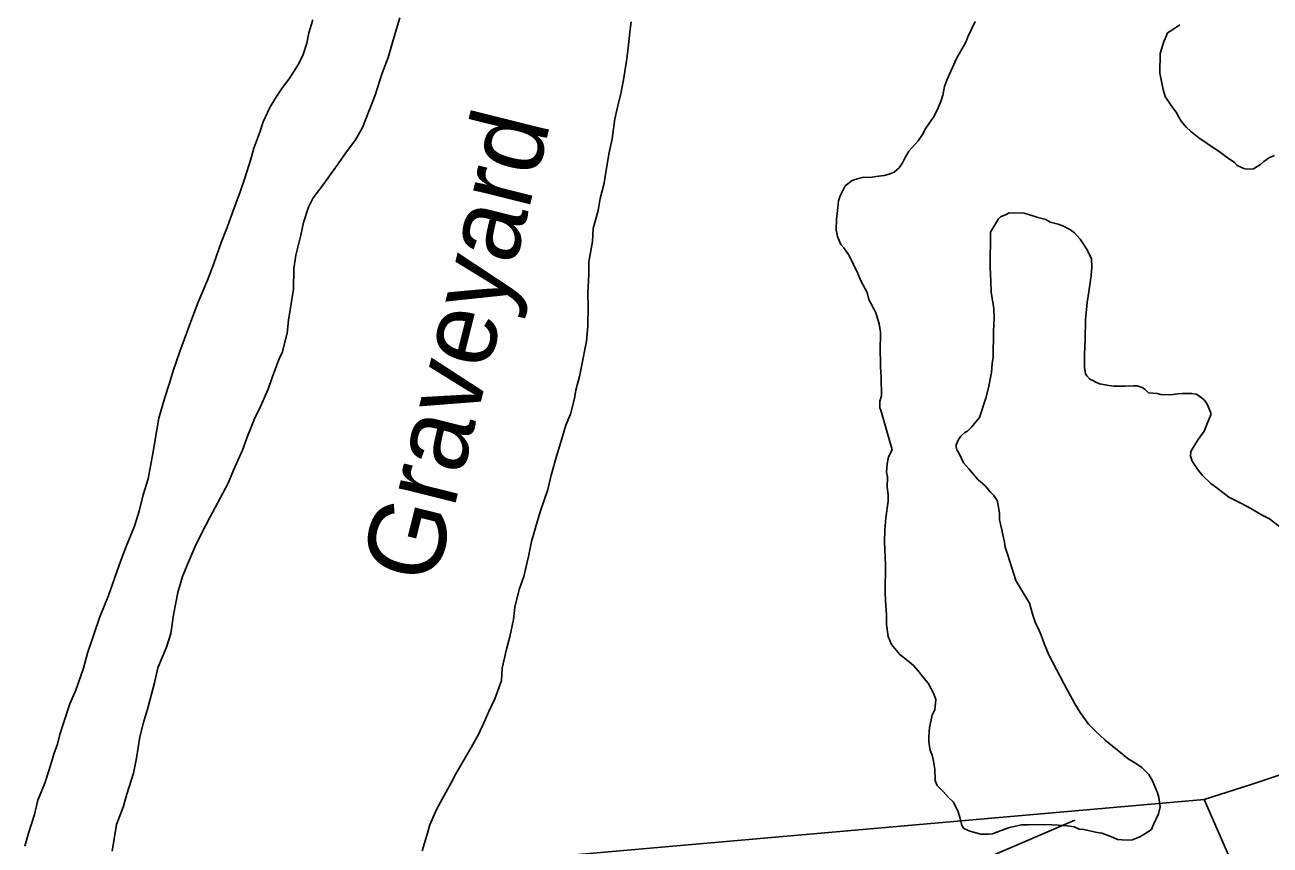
# Model space of a CAD drawing. Extents: x 3161514 to 3199414, y 831166 to 856601.
# Drawn here: x 3169027 to 3170653, y 839105 to 840176 of the extents above; entities that cross this region are included whole.
import ezdxf

# ---------------------------------------------------------------- set-up
doc = ezdxf.new("R2010")
doc.units = 0
for name, color, linetype in [('V-RIVR-IDEN', 7, 'Continuous'), ('V-SITE-VEGE', 7, 'Continuous'), ('V-TOPO-SHOR', 7, 'Continuous')]:
    doc.layers.add(name, color=color, linetype=linetype)

msp = doc.modelspace()

# ---------------------------------------------------------------- linework, layer by layer
at = {"layer": 'V-SITE-VEGE'}
for p, q in [((3169516.6, 840185.6), (3169511.2, 840166.9)), ((3169397.9, 840165.9), (3169403.2, 840182.9)), ((3169817.2, 840167), (3169819, 840180.6)), ((3170268, 840180.8), (3170258.7, 840160.8)), ((3170519.3, 840166.3), (3170523.9, 840168.9)), ((3170523.9, 840168.9), (3170535.7, 840176.5)), ((3169390.7, 840137.9), (3169395.2, 840152.4)), ((3169395.2, 840152.4), (3169397.9, 840165.9)), ((3169511.2, 840166.9), (3169501.4, 840133.8)), ((3169815.2, 840146.6), (3169817.2, 840167)), ((3170256, 840153.7), (3170244, 840132.5)), ((3170258.7, 840160.8), (3170256, 840153.7)), ((3170509.9, 840139.2), (3170514.6, 840154.7)), ((3170514.6, 840154.7), (3170517.3, 840160.5)), ((3170517.3, 840160.5), (3170518.6, 840163.7)), ((3170518.6, 840163.7), (3170519.3, 840166.3)), ((3169384.6, 840125.2), (3169390.7, 840137.9)), ((3169813.3, 840132.1), (3169815.2, 840146.6)), ((3170509.5, 840113.3), (3170509.9, 840139.2)), ((3169372.4, 840105.8), (3169384.6, 840125.2)), ((3169501.4, 840133.8), (3169493.5, 840113.5)), ((3169809.5, 840107.4), (3169813.3, 840132.1)), ((3170244, 840132.5), (3170231.3, 840104.2)), ((3169363.7, 840094.8), (3169372.4, 840105.8)), ((3169493.5, 840113.5), (3169484.5, 840084.7)), ((3169805.9, 840088.7), (3169809.5, 840107.4)), ((3170231.3, 840104.2), (3170228, 840095.8)), ((3170513.8, 840091.9), (3170509.5, 840113.3)), ((3169353.3, 840079.6), (3169363.7, 840094.8)), ((3169801.3, 840070.9), (3169805.9, 840088.7)), ((3170228, 840095.8), (3170225.9, 840084.8)), ((3170516.2, 840082.8), (3170513.8, 840091.9)), ((3169347.1, 840068.7), (3169353.3, 840079.6)), ((3169484.5, 840084.7), (3169467.8, 840042.3)), ((3169797.7, 840053.9), (3169801.3, 840070.9)), ((3170223.8, 840077.7), (3170219.8, 840068)), ((3170225.9, 840084.8), (3170223.8, 840077.7)), ((3170525.1, 840069.7), (3170516.2, 840082.8)), ((3169338.4, 840050), (3169347.1, 840068.7)), ((3169793.9, 840027.6), (3169797.7, 840053.9)), ((3170214.5, 840057.1), (3170203.9, 840041.7)), ((3170219.8, 840068), (3170214.5, 840057.1)), ((3170530.9, 840062.5), (3170525.1, 840069.7)), ((3170534, 840055.9), (3170530.9, 840062.5)), ((3170537.2, 840050.7), (3170534, 840055.9)), ((3169333.9, 840036.5), (3169338.4, 840050)), ((3169467.8, 840042.3), (3169459, 840026.2)), ((3170203.9, 840041.7), (3170199.2, 840033.3)), ((3170544.2, 840042.2), (3170537.2, 840050.7)), ((3170549.3, 840037.6), (3170544.2, 840042.2)), ((3169326, 840015.3), (3169333.9, 840036.5)), ((3169459, 840026.2), (3169445.1, 840007.7)), ((3169790.3, 840009.7), (3169793.9, 840027.6)), ((3170193.9, 840025), (3170190, 840020.5)), ((3170199.2, 840033.3), (3170193.9, 840025)), ((3170560.2, 840029), (3170549.3, 840037.6)), ((3170571.1, 840021.7), (3170560.2, 840029)), ((3170588.5, 840009.8), (3170571.1, 840021.7)), ((3169322.3, 840000.8), (3169326, 840015.3)), ((3169445.1, 840007.7), (3169436.4, 839995)), ((3169785.7, 839984.2), (3169790.3, 840009.7)), ((3170181.4, 840011.5), (3170176.8, 840003.2)), ((3170190, 840020.5), (3170181.4, 840011.5)), ((3170597.4, 840003.2), (3170588.5, 840009.8)), ((3170659, 840005.6), (3170652.5, 840003.1)), ((3169314.3, 839976.2), (3169322.3, 840000.8)), ((3169436.4, 839995), (3169426.9, 839982.3)), ((3170168.8, 839989.7), (3170162.3, 839983.9)), ((3170173.5, 839996.1), (3170168.8, 839989.7)), ((3170176.8, 840003.2), (3170173.5, 839996.1)), ((3170607.1, 839996.6), (3170597.4, 840003.2)), ((3170610.3, 839992.7), (3170607.1, 839996.6)), ((3170619.3, 839988.6), (3170610.3, 839992.7)), ((3170640.7, 839994.2), (3170631.6, 839988.5)), ((3170645.3, 839998), (3170640.7, 839994.2)), ((3170652.5, 840003.1), (3170645.3, 839998)), ((3169308.1, 839958.4), (3169314.3, 839976.2)), ((3169426.9, 839982.3), (3169417.3, 839968.8)), ((3169783.8, 839969.8), (3169785.7, 839984.2)), ((3170107.7, 839973), (3170098.5, 839966)), ((3170114.2, 839975.5), (3170107.7, 839973)), ((3170122.6, 839977.3), (3170114.2, 839975.5)), ((3170131.1, 839977.2), (3170122.6, 839977.3)), ((3170138.9, 839978.4), (3170131.1, 839977.2)), ((3170149.2, 839979.6), (3170138.9, 839978.4)), ((3170155.8, 839981.4), (3170149.2, 839979.6)), ((3170162.3, 839983.9), (3170155.8, 839981.4)), ((3170623.2, 839987.9), (3170619.3, 839988.6)), ((3170631.6, 839988.5), (3170623.2, 839987.9)), ((3169298.4, 839931.3), (3169308.1, 839958.4)), ((3169417.3, 839968.8), (3169403.4, 839950.3)), ((3169778.4, 839949.4), (3169783.8, 839969.8)), ((3170098.5, 839966), (3170091.8, 839953.1)), ((3169403.4, 839950.3), (3169397.3, 839938.4)), ((3169775.6, 839934.1), (3169778.4, 839949.4)), ((3170089.8, 839946.7), (3170088.3, 839933.7)), ((3170091.8, 839953.1), (3170089.8, 839946.7)), ((3169291.3, 839911.8), (3169298.4, 839931.3)), ((3169397.3, 839938.4), (3169391.1, 839918.1)), ((3169769.3, 839910.3), (3169775.6, 839934.1)), ((3170088.3, 839933.7), (3170086.9, 839922.7)), ((3170298.8, 839923.1), (3170301.5, 839925.6)), ((3170301.5, 839925.6), (3170308.6, 839928.8)), ((3170308.6, 839928.8), (3170312.6, 839930.7)), ((3170312.6, 839930.7), (3170332, 839930.4)), ((3170332, 839930.4), (3170343.6, 839927)), ((3170343.6, 839927), (3170350.1, 839925)), ((3170350.1, 839925), (3170360.4, 839922.2)), ((3169283.4, 839892.3), (3169291.3, 839911.8)), ((3169391.1, 839918.1), (3169387.4, 839901.9)), ((3169768.2, 839893.3), (3169769.3, 839910.3)), ((3170086.9, 839922.7), (3170086.7, 839908.5)), ((3170086.7, 839908.5), (3170088.5, 839900)), ((3170288.2, 839905.7), (3170298.8, 839923.1)), ((3170360.4, 839922.2), (3170366.2, 839918.9)), ((3170366.2, 839918.9), (3170376.5, 839916.2)), ((3170376.5, 839916.2), (3170383.6, 839913.5)), ((3170383.6, 839913.5), (3170392.6, 839908.8)), ((3170392.6, 839908.8), (3170397.8, 839904.8)), ((3169273.6, 839863.5), (3169283.4, 839892.3)), ((3169387.4, 839901.9), (3169381.1, 839875.6)), ((3169763.6, 839866.9), (3169768.2, 839893.3)), ((3170088.5, 839900), (3170092.9, 839889.6)), ((3170287.6, 839859.7), (3170288.2, 839905.7)), ((3170397.8, 839904.8), (3170405.4, 839896.3)), ((3170405.4, 839896.3), (3170409.9, 839889.8)), ((3169381.1, 839875.6), (3169378.3, 839857.8)), ((3170092.9, 839889.6), (3170096.7, 839885)), ((3170096.7, 839885), (3170103.7, 839875.2)), ((3170103.7, 839875.2), (3170115.1, 839851.7)), ((3170409.9, 839889.8), (3170413.7, 839883.9)), ((3170413.7, 839883.9), (3170418.1, 839875.4)), ((3170418.1, 839875.4), (3170420, 839870.8)), ((3169265.6, 839843.1), (3169273.6, 839863.5)), ((3169763.4, 839850.7), (3169763.6, 839866.9)), ((3170288.6, 839841.5), (3170287.6, 839859.7)), ((3170420.5, 839859.8), (3170419.7, 839848.8)), ((3170420, 839870.8), (3170420.5, 839859.8)), ((3169253.3, 839814.3), (3169265.6, 839843.1)), ((3169378.3, 839857.8), (3169377.9, 839831.3)), ((3169762.2, 839826), (3169763.4, 839850.7)), ((3170115.1, 839851.7), (3170118.8, 839841.9)), ((3170419.7, 839848.8), (3170416.8, 839827.5)), ((3169377.9, 839831.3), (3169375.2, 839815.2)), ((3170118.8, 839841.9), (3170127.1, 839826.9)), ((3170127.1, 839826.9), (3170129.5, 839817.8)), ((3170289.1, 839826.6), (3170288.6, 839841.5)), ((3170292.7, 839806.5), (3170289.1, 839826.6)), ((3170416.8, 839827.5), (3170414.6, 839813.9)), ((3169246.2, 839795.7), (3169253.3, 839814.3)), ((3169375.2, 839815.2), (3169371.4, 839790.5)), ((3169762.8, 839809), (3169762.2, 839826)), ((3170129.5, 839817.8), (3170136.5, 839804.7)), ((3170414.6, 839813.9), (3170412.4, 839791.2)), ((3169229.4, 839749.9), (3169246.2, 839795.7)), ((3169762.4, 839782.6), (3169762.8, 839809)), ((3170136.5, 839804.7), (3170138.3, 839800.2)), ((3170138.3, 839800.2), (3170142.7, 839785.9)), ((3170293.2, 839793.5), (3170292.7, 839806.5)), ((3169371.4, 839790.5), (3169369.5, 839773.5)), ((3169760.5, 839763), (3169762.4, 839782.6)), ((3170142.7, 839785.9), (3170144.5, 839774.8)), ((3170292.3, 839776), (3170293.2, 839793.5)), ((3170412.4, 839791.2), (3170412, 839765.3)), ((3169369.5, 839773.5), (3169363.2, 839748)), ((3169754, 839729.9), (3169760.5, 839763)), ((3170144.5, 839774.8), (3170144.1, 839749.5)), ((3170291.8, 839742.3), (3170292.3, 839776)), ((3170412, 839765.3), (3170411.1, 839745.9)), ((3169220.5, 839724.4), (3169229.4, 839749.9)), ((3169363.2, 839748), (3169359.7, 839741.3)), ((3170144.1, 839749.5), (3170144.6, 839737.2)), ((3170411.1, 839745.9), (3170410.9, 839729)), ((3169359.7, 839741.3), (3169349.9, 839715.8)), ((3169751.3, 839717.1), (3169754, 839729.9)), ((3170144.6, 839737.2), (3170144.5, 839728.8)), ((3170144.5, 839728.8), (3170145.6, 839717.1)), ((3170289.6, 839722.3), (3170290.4, 839733.9)), ((3170290.4, 839733.9), (3170291.8, 839742.3)), ((3170410.9, 839729), (3170412.1, 839720.6)), ((3169216.1, 839708.3), (3169220.5, 839724.4)), ((3169349.9, 839715.8), (3169344.6, 839700.6)), ((3169746.8, 839699.3), (3169751.3, 839717.1)), ((3170145.6, 839717.1), (3170145.5, 839709.3)), ((3170285.4, 839702.2), (3170289.6, 839722.3)), ((3170412.1, 839720.6), (3170414, 839718)), ((3170414, 839718), (3170417.8, 839713.4)), ((3170417.8, 839713.4), (3170421.7, 839712)), ((3169209.8, 839689.7), (3169216.1, 839708.3)), ((3169344.6, 839700.6), (3169334.9, 839677.7)), ((3169744.9, 839688.2), (3169746.8, 839699.3)), ((3170145.5, 839709.3), (3170146, 839698.3)), ((3170146, 839698.3), (3170145.9, 839691.8)), ((3170282, 839688.7), (3170285.4, 839702.2)), ((3170421.7, 839712), (3170424.9, 839710)), ((3170424.9, 839710), (3170430.7, 839707.4)), ((3170430.7, 839707.4), (3170443, 839705.2)), ((3170443, 839705.2), (3170449.4, 839704.5)), ((3170449.4, 839704.5), (3170463.7, 839704.3)), ((3170463.7, 839704.3), (3170474.7, 839704.8)), ((3170474.7, 839704.8), (3170479.9, 839704.7)), ((3170479.9, 839704.7), (3170486.4, 839702.7)), ((3170486.4, 839702.7), (3170490.2, 839700.1)), ((3170490.2, 839700.1), (3170494.7, 839695.5)), ((3169201.8, 839662.5), (3169209.8, 839689.7)), ((3169739.5, 839667.9), (3169744.9, 839688.2)), ((3170143.9, 839684.7), (3170143.8, 839675.7)), ((3170145.9, 839691.8), (3170143.9, 839684.7)), ((3170273.9, 839663.5), (3170282, 839688.7)), ((3170494.7, 839695.5), (3170505.7, 839694.7)), ((3170505.7, 839694.7), (3170510.9, 839693.3)), ((3170510.9, 839693.3), (3170523.8, 839693.1)), ((3170523.8, 839693.1), (3170532.3, 839694.3)), ((3170532.3, 839694.3), (3170538.7, 839694.8)), ((3170538.7, 839694.8), (3170551.1, 839694.7)), ((3170551.1, 839694.7), (3170556.9, 839694)), ((3170556.9, 839694), (3170560.1, 839692)), ((3170560.1, 839692), (3170567.8, 839686)), ((3170567.8, 839686), (3170571, 839680.8)), ((3170571, 839680.8), (3170576, 839669.7)), ((3169334.9, 839677.7), (3169327, 839661.6)), ((3169733.4, 839653.5), (3169739.5, 839667.9)), ((3170143.8, 839675.7), (3170145, 839673.1)), ((3170145, 839673.1), (3170159.9, 839621)), ((3170576, 839667.1), (3170570.6, 839654.2)), ((3170576, 839669.7), (3170576, 839667.1)), ((3169199, 839644.6), (3169201.8, 839662.5)), ((3169327, 839661.6), (3169317.3, 839637.9)), ((3169727.1, 839631.4), (3169733.4, 839653.5)), ((3170258.1, 839645.6), (3170264, 839651.3)), ((3170264, 839651.3), (3170267.3, 839655.8)), ((3170267.3, 839655.8), (3170273.9, 839663.5)), ((3170570.6, 839654.2), (3170567.2, 839645.8)), ((3169194.3, 839616.6), (3169199, 839644.6)), ((3169317.3, 839637.9), (3169311.1, 839620.9)), ((3169721.8, 839614.4), (3169727.1, 839631.4)), ((3170243.6, 839627.6), (3170246.3, 839634.7)), ((3170246.3, 839634.7), (3170249.6, 839639.2)), ((3170249.6, 839639.2), (3170254.8, 839643.7)), ((3170254.8, 839643.7), (3170258.1, 839645.6)), ((3170559.3, 839634.9), (3170556.6, 839629.8)), ((3170567.2, 839645.8), (3170559.3, 839634.9)), ((3169187.9, 839583.4), (3169194.3, 839616.6)), ((3169311.1, 839620.9), (3169299.7, 839594.7)), ((3170159.9, 839621), (3170155.2, 839612)), ((3170243.5, 839625), (3170243.6, 839627.6)), ((3170244.1, 839621.1), (3170243.5, 839625)), ((3170246.7, 839617.2), (3170244.1, 839621.1)), ((3170253, 839604.2), (3170246.7, 839617.2)), ((3170550, 839618.9), (3170549.3, 839613)), ((3170556.6, 839629.8), (3170550, 839618.9)), ((3169714.6, 839588.1), (3169721.8, 839614.4)), ((3170153.1, 839602.9), (3170152.3, 839591.9)), ((3170155.2, 839612), (3170153.1, 839602.9)), ((3170260, 839596.3), (3170253, 839604.2)), ((3170549.3, 839613), (3170551.8, 839606.5)), ((3170551.8, 839606.5), (3170560, 839594.1)), ((3169181.7, 839562.2), (3169187.9, 839583.4)), ((3169299.7, 839594.7), (3169292.7, 839577.7)), ((3169710.1, 839569.4), (3169714.6, 839588.1)), ((3170152.3, 839591.9), (3170153.5, 839586.1)), ((3170153.5, 839586.1), (3170153.4, 839572.5)), ((3170272.1, 839581.9), (3170260, 839596.3)), ((3170560, 839594.1), (3170565.1, 839587.5)), ((3170565.1, 839587.5), (3170576, 839577)), ((3169292.7, 839577.7), (3169278.7, 839551.5)), ((3169700.3, 839541.4), (3169710.1, 839569.4)), ((3170153.4, 839572.5), (3170154.5, 839562.7)), ((3170281.1, 839574), (3170272.1, 839581.9)), ((3170288.1, 839566.1), (3170281.1, 839574)), ((3170292.6, 839561.5), (3170288.1, 839566.1)), ((3170576, 839577), (3170583.7, 839571.7)), ((3170583.7, 839571.7), (3170599.7, 839559.2)), ((3169176.3, 839541), (3169181.7, 839562.2)), ((3169278.7, 839551.5), (3169269, 839533.8)), ((3170154.4, 839554.3), (3170151.5, 839532.3)), ((3170154.5, 839562.7), (3170154.4, 839554.3)), ((3170297, 839554.9), (3170292.6, 839561.5)), ((3170298.2, 839549.1), (3170297, 839554.9)), ((3170599.7, 839559.2), (3170617.1, 839550.5)), ((3170617.1, 839550.5), (3170628.1, 839544.5)), ((3169170, 839521.5), (3169176.3, 839541)), ((3169269, 839533.8), (3169256.8, 839510.1)), ((3169697.6, 839531.3), (3169700.3, 839541.4)), ((3170300, 839538), (3170298.2, 839549.1)), ((3170299.9, 839529.6), (3170300, 839538)), ((3170628.1, 839544.5), (3170642.9, 839535.9)), ((3170642.9, 839535.9), (3170652.5, 839531.2)), ((3169158.5, 839492.7), (3169170, 839521.5)), ((3169688.7, 839501.6), (3169697.6, 839531.3)), ((3170151.5, 839532.3), (3170150, 839516.8)), ((3170303, 839516.6), (3170299.9, 839529.6)), ((3170652.5, 839531.2), (3170666, 839520.7)), ((3169256.8, 839510.1), (3169248.9, 839494)), ((3169685, 839482), (3169688.7, 839501.6)), ((3170150, 839516.8), (3170149.8, 839501.2)), ((3170149.8, 839501.2), (3170151.3, 839470.7)), ((3170304.2, 839510.1), (3170303, 839516.6)), ((3170306.6, 839500.4), (3170304.2, 839510.1)), ((3169152.4, 839476.6), (3169158.5, 839492.7)), ((3169248.9, 839494), (3169239.2, 839470.3)), ((3170307.2, 839493.9), (3170306.6, 839500.4)), ((3170310.3, 839484.8), (3170307.2, 839493.9)), ((3170316.5, 839465.9), (3170310.3, 839484.8)), ((3169136.4, 839430.8), (3169152.4, 839476.6)), ((3169239.2, 839470.3), (3169233, 839455.9)), ((3169678.7, 839455.7), (3169685, 839482)), ((3170151.3, 839470.7), (3170150.8, 839435.1)), ((3169233, 839455.9), (3169226.8, 839434.6)), ((3169672.5, 839438.7), (3169678.7, 839455.7)), ((3170321.5, 839450.3), (3170316.5, 839465.9)), ((3169667.1, 839415.8), (3169672.5, 839438.7)), ((3170339.2, 839420.8), (3170321.5, 839450.3)), ((3169124.9, 839402.8), (3169136.4, 839430.8)), ((3169226.8, 839434.6), (3169221.3, 839405.7)), ((3170150.8, 839435.1), (3170151.3, 839424.1)), ((3170151.3, 839424.1), (3170152.4, 839405.9)), ((3170343.6, 839405.2), (3170339.2, 839420.8)), ((3169221.3, 839405.7), (3169217.5, 839381.1)), ((3169665.1, 839399.6), (3169667.1, 839415.8)), ((3170152.4, 839405.9), (3170152.2, 839393)), ((3170346.7, 839396.1), (3170343.6, 839405.2)), ((3169108.9, 839355.3), (3169124.9, 839402.8)), ((3169660.5, 839376.7), (3169665.1, 839399.6)), ((3170152.2, 839393), (3170154.6, 839377.4)), ((3170351.7, 839385), (3170346.7, 839396.1)), ((3169217.5, 839381.1), (3169212.2, 839363.3)), ((3169656.1, 839360.6), (3169660.5, 839376.7)), ((3170154.6, 839377.4), (3170158.9, 839366.9)), ((3170354.2, 839379.2), (3170351.7, 839385)), ((3170358.6, 839366.8), (3170354.2, 839379.2)), ((3169103.6, 839335.8), (3169108.9, 839355.3)), ((3169212.2, 839363.3), (3169200.7, 839336.2)), ((3169650.6, 839335.9), (3169656.1, 839360.6)), ((3170158.9, 839366.9), (3170169.8, 839353.8)), ((3170364.9, 839352.4), (3170358.6, 839366.8)), ((3170169.8, 839353.8), (3170180, 839345.9)), ((3170180, 839345.9), (3170187.7, 839339.3)), ((3170187.7, 839339.3), (3170193.5, 839332.8)), ((3170379.4, 839325), (3170364.9, 839352.4)), ((3169093.8, 839307), (3169103.6, 839335.8)), ((3169200.7, 839336.2), (3169196.2, 839316.6)), ((3169649.5, 839319.7), (3169650.6, 839335.9)), ((3170193.5, 839332.8), (3170201.8, 839322.3)), ((3170201.8, 839322.3), (3170206.9, 839316.4)), ((3170383.8, 839315.9), (3170379.4, 839325)), ((3169085.9, 839289.2), (3169093.8, 839307)), ((3169196.2, 839316.6), (3169188.1, 839285.2)), ((3169640.7, 839296), (3169649.5, 839319.7)), ((3170206.9, 839316.4), (3170213.8, 839303.3)), ((3170398.3, 839289.1), (3170383.8, 839315.9)), ((3169632.8, 839279.1), (3169640.7, 839296)), ((3170213.8, 839303.3), (3170216.9, 839294.8)), ((3170216.9, 839294.8), (3170215.5, 839281.3)), ((3169077, 839262.9), (3169085.9, 839289.2)), ((3169188.1, 839285.2), (3169181.8, 839264.8)), ((3169626.6, 839264.7), (3169632.8, 839279.1)), ((3170212.1, 839274.8), (3170208.6, 839258)), ((3170215.5, 839281.3), (3170212.1, 839274.8)), ((3170405.3, 839278), (3170398.3, 839289.1)), ((3170416.1, 839262.9), (3170405.3, 839278)), ((3169072.5, 839249.3), (3169077, 839262.9)), ((3169181.8, 839264.8), (3169177.3, 839246.2)), ((3169619.6, 839249.4), (3169626.6, 839264.7)), ((3170208.6, 839258), (3170207.8, 839246.4)), ((3170424.4, 839254.4), (3170416.1, 839262.9)), ((3169069.8, 839236.6), (3169072.5, 839249.3)), ((3169177.3, 839246.2), (3169172.7, 839218.1)), ((3169608.2, 839229.1), (3169619.6, 839249.4)), ((3170207.8, 839246.4), (3170207.7, 839239.2)), ((3170437.9, 839241.9), (3170424.4, 839254.4)), ((3170447.5, 839234), (3170437.9, 839241.9)), ((3169058.2, 839201.8), (3169065.4, 839224.7)), ((3169065.4, 839224.7), (3169069.8, 839236.6)), ((3169589.9, 839197.9), (3169608.2, 839229.1)), ((3170207.7, 839239.2), (3170209.5, 839228.8)), ((3170209.5, 839228.8), (3170212.1, 839222.3)), ((3170460.3, 839224.1), (3170447.5, 839234)), ((3169172.7, 839218.1), (3169169, 839198.5)), ((3170212.1, 839222.3), (3170213.9, 839214.5)), ((3170213.9, 839214.5), (3170215.7, 839204.1)), ((3170468, 839217.5), (3170460.3, 839224.1)), ((3170478.9, 839210.9), (3170468, 839217.5)), ((3170486, 839206.2), (3170478.9, 839210.9)), ((3169052.9, 839185.7), (3169058.2, 839201.8)), ((3169169, 839198.5), (3169160.1, 839171.4)), ((3169583.8, 839186), (3169589.9, 839197.9)), ((3170215.7, 839204.1), (3170216.1, 839189.2)), ((3170494.9, 839197), (3170486, 839206.2)), ((3170500, 839188.5), (3170494.9, 839197)), ((3169044.1, 839163.6), (3169052.9, 839185.7)), ((3169572.4, 839165.7), (3169583.8, 839186)), ((3170216.1, 839189.2), (3170218.6, 839182.7)), ((3170218.6, 839182.7), (3170226.3, 839174.8)), ((3170506.3, 839172.9), (3170500, 839188.5)), ((3169039.6, 839144.9), (3169044.1, 839163.6)), ((3169160.1, 839171.4), (3169155.6, 839154.4)), ((3169564.6, 839151.3), (3169572.4, 839165.7)), ((3170226.3, 839174.8), (3170233.3, 839166.9)), ((3170233.3, 839166.9), (3170239.7, 839161)), ((3170239.7, 839161), (3170246, 839148)), ((3170508.1, 839167), (3170506.3, 839172.9)), ((3170509.9, 839154.7), (3170508.1, 839167)), ((3169031.6, 839120.3), (3169039.6, 839144.9)), ((3169155.6, 839154.4), (3169146.8, 839131.5)), ((3169555.8, 839131), (3169564.6, 839151.3)), ((3170246, 839148), (3170248.5, 839139.5)), ((3170501.2, 839131.5), (3170507.8, 839145.6)), ((3170507.8, 839145.6), (3170509.9, 839154.7)), ((3169146.8, 839131.5), (3169141.2, 839096.7)), ((3169552.2, 839117.4), (3169555.8, 839131)), ((3170248.5, 839139.5), (3170251, 839130.4)), ((3170251, 839130.4), (3170253.5, 839126.5)), ((3170302.1, 839123.9), (3170313.1, 839127.6)), ((3170313.1, 839127.6), (3170328.8, 839131.3)), ((3170328.8, 839131.3), (3170337.2, 839131.1)), ((3170337.2, 839131.1), (3170346.3, 839131.7)), ((3170346.3, 839131.7), (3170368.3, 839131.4)), ((3170368.3, 839131.4), (3170376.7, 839130.6)), ((3170376.7, 839130.6), (3170388.4, 839129.8)), ((3170388.4, 839129.8), (3170397.4, 839128.4)), ((3170397.4, 839128.4), (3170403.9, 839125.7)), ((3170498.5, 839125), (3170501.2, 839131.5)), ((3169027.1, 839103.4), (3169031.6, 839120.3)), ((3169545.9, 839097.1), (3169552.2, 839117.4)), ((3170253.5, 839126.5), (3170261.2, 839123.1)), ((3170261.2, 839123.1), (3170275.4, 839119)), ((3170275.4, 839119), (3170285.8, 839118.9)), ((3170285.8, 839118.9), (3170291, 839119.5)), ((3170291, 839119.5), (3170302.1, 839123.9)), ((3170403.9, 839125.7), (3170410.3, 839125)), ((3170410.3, 839125), (3170425.2, 839121.5)), ((3170425.2, 839121.5), (3170433.6, 839120.1)), ((3170433.6, 839120.1), (3170445.2, 839116)), ((3170445.2, 839116), (3170454.2, 839112)), ((3170454.2, 839112), (3170466.5, 839111.2)), ((3170466.5, 839111.2), (3170473.7, 839111.8)), ((3170473.7, 839111.8), (3170483.4, 839115.5)), ((3170483.4, 839115.5), (3170490, 839119.3)), ((3170490, 839119.3), (3170498.5, 839125))]:
    msp.add_line(p, q, dxfattribs=at)
at = {"layer": 'V-TOPO-SHOR'}
for points in [[(3170944.6, 840674.5), (3170938.3, 840560.8), (3170881.4, 840504), (3170843.5, 840466.1), (3170805.6, 840421.9), (3170786.7, 840339.8), (3170811.9, 840270.3), (3170830.9, 840200.8), (3170830.9, 840118.7), (3170818.3, 840061.9), (3170793, 839960.8), (3170811.9, 839866.1), (3170830.9, 839796.6), (3170843.5, 839701.9), (3170849.8, 839632.4), (3170830.9, 839512.4), (3170824.6, 839455.6), (3170818.3, 839411.4), (3170805.6, 839386.1), (3170805.6, 839348.2), (3170786.7, 839272.4), (3170704.6, 839209.3), (3170628.8, 839184), (3170567.2, 839164.3)], [(3169651.4, 838668.5), (3169739.8, 839091.6), (3170567.2, 839164.3), (3170624, 839034.8), (3170854.6, 839050.6), (3171315.6, 839075.8), (3172124.1, 839060), (3172373.5, 839069.5)], [(3170398.3, 839137.4), (3170287.7, 839090)]]:
    msp.add_lwpolyline(points, dxfattribs=at)

# ---------------------------------------------------------------- texts
at = {"layer": 'V-RIVR-IDEN'}
msp.add_text('Graveyard', height=100, rotation=75.9638, dxfattribs=at).set_placement((3169562.3, 839442.6))

doc.saveas('drawing.dxf')
